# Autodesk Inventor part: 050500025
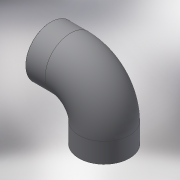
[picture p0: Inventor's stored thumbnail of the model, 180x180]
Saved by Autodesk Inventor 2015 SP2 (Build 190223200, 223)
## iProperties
Created: 2017-10
Part Number: 050500025
Material: Generic
Description: PLASSON 90° ELBOW-CEMENT PVC 25
Document SubType Name: Modeling
Designer: KIM
Density: 1 g/cm^3
Appearance: Default
Author: KIM
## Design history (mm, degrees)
derived "050500.ipt"
feature "Solid1::050500.ipt"
tag "TaggingFeature1"
body "Solid1"
other parameters: "d1" = 31, "d4" = 25, "d5" = 22.5, "d7" = 0.25, "d9" = 31, "d10" = 32.5, "d13" = 90 deg, "d18" = 14, "d19" = 90 deg, "d20" = 25, "d21" = 19, "d22" = 0, "d24" = 90 deg, "d26" = 22.5, "d27" = 90 deg, "d_" = 25, "E_" = 31, "H_" = 48, "l_" = 19, "Z_" = 14
